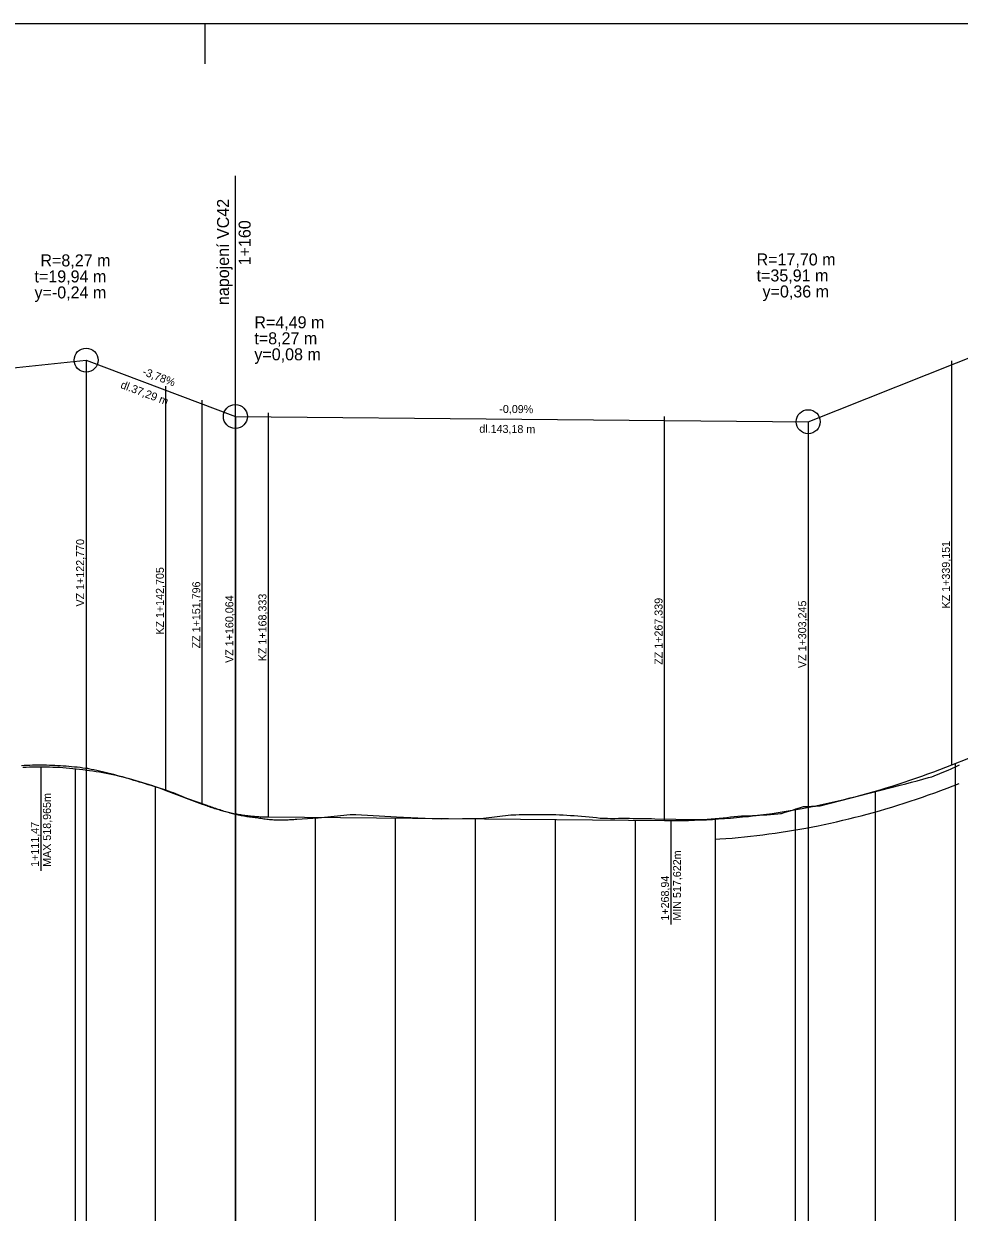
# Model space of a CAD drawing. Extents: x -632716 to -629545, y -1094726 to -1088285.
# Drawn here: x -631412.3 to -631178.5, y -1092500.3 to -1092203.3 of the extents above; entities that cross this region are included whole.
import ezdxf

# ---------------------------------------------------------------- set-up
doc = ezdxf.new("R2010")
doc.units = 0
for name, color, linetype in [('20', 7, 'Continuous'), ('Default', 7, 'Continuous'), ('formát', 7, 'Continuous'), ('PŘÍKOP', 7, 'Continuous'), ('SKLONY_NIVELETA', 7, 'Continuous'), ('SKLONY_POPIS', 7, 'Continuous'), ('TECNY_NIVELETA', 7, 'Continuous'), ('VOZOVKA', 7, 'Continuous')]:
    doc.layers.add(name, color=color, linetype=linetype)

msp = doc.modelspace()

# ---------------------------------------------------------------- linework, layer by layer
at = {"layer": '20'}
for points in [[(-631399.44, -1092389.4), (-631399.44, -1092678.62), (-631399.44, -1092728.62), (-631399.44, -1092668.62)], [(-631179.44, -1092388.14), (-631179.44, -1092678.62), (-631179.44, -1092728.62), (-631179.44, -1092668.62)], [(-631379.44, -1092393.88), (-631379.44, -1092678.62), (-631379.44, -1092728.62), (-631379.44, -1092668.62)], [(-631199.44, -1092395.04), (-631199.44, -1092678.62), (-631199.44, -1092728.62), (-631199.44, -1092668.62)], [(-631359.44, -1092400.64), (-631359.44, -1092678.62), (-631359.44, -1092728.62), (-631359.44, -1092668.62)], [(-631339.44, -1092401.6), (-631339.44, -1092678.62), (-631339.44, -1092728.62), (-631339.44, -1092668.62)], [(-631219.44, -1092399.67), (-631219.44, -1092678.62), (-631219.44, -1092728.62), (-631219.44, -1092668.62)], [(-631319.44, -1092401.78), (-631319.44, -1092678.62), (-631319.44, -1092728.62), (-631319.44, -1092668.62)], [(-631299.44, -1092401.96), (-631299.44, -1092678.62), (-631299.44, -1092728.62), (-631299.44, -1092668.62)], [(-631279.44, -1092402.14), (-631279.44, -1092678.62), (-631279.44, -1092728.62), (-631279.44, -1092668.62)], [(-631259.44, -1092402.32), (-631259.44, -1092678.62), (-631259.44, -1092728.62), (-631259.44, -1092668.62)], [(-631239.44, -1092402.05), (-631239.44, -1092678.62), (-631239.44, -1092728.62), (-631239.44, -1092668.62)]]:
    msp.add_lwpolyline(points, dxfattribs=at)
at = {"layer": 'Default'}
for p, q in [((-631180.29, -1092388.48), (-631087.13, -1092351.53)), ((-631180.29, -1092388.48), (-631087.13, -1092351.53)), ((-631376.74, -1092394.86), (-631367.65, -1092398.3)), ((-631376.74, -1092394.86), (-631367.65, -1092398.3)), ((-631351.11, -1092401.49), (-631252.11, -1092402.39)), ((-631351.11, -1092401.49), (-631252.11, -1092402.39))]:
    msp.add_line(p, q, dxfattribs=at)
for points in [[(-631412.46, -1092389.09), (-631411.63, -1092389.04), (-631410.8, -1092389.01), (-631409.97, -1092388.99), (-631409.13, -1092388.97), (-631408.3, -1092388.96), (-631407.47, -1092388.97), (-631406.64, -1092388.97), (-631405.81, -1092388.99), (-631404.98, -1092389.02), (-631404.15, -1092389.05), (-631403.32, -1092389.09), (-631402.49, -1092389.15), (-631401.66, -1092389.2), (-631400.83, -1092389.27), (-631400, -1092389.35), (-631399.17, -1092389.43), (-631398.34, -1092389.52), (-631397.51, -1092389.63), (-631395.84, -1092389.85), (-631395.01, -1092389.98), (-631394.18, -1092390.11), (-631393.35, -1092390.26), (-631392.52, -1092390.41), (-631391.69, -1092390.57), (-631390.86, -1092390.73), (-631390.03, -1092390.91), (-631389.2, -1092391.09), (-631388.37, -1092391.29), (-631387.54, -1092391.49), (-631386.71, -1092391.7), (-631385.88, -1092391.92), (-631385.05, -1092392.14), (-631384.22, -1092392.38), (-631383.38, -1092392.62), (-631382.55, -1092392.87), (-631381.72, -1092393.13), (-631380.89, -1092393.4), (-631380.06, -1092393.67), (-631379.23, -1092393.96), (-631378.4, -1092394.25), (-631377.57, -1092394.55), (-631376.74, -1092394.86)], [(-631412.46, -1092389.09), (-631411.63, -1092389.04), (-631410.8, -1092389.01), (-631409.97, -1092388.99), (-631409.13, -1092388.97), (-631408.3, -1092388.96), (-631407.47, -1092388.97), (-631406.64, -1092388.97), (-631405.81, -1092388.99), (-631404.98, -1092389.02), (-631404.15, -1092389.05), (-631403.32, -1092389.09), (-631402.49, -1092389.15), (-631401.66, -1092389.2), (-631400.83, -1092389.27), (-631400, -1092389.35), (-631399.17, -1092389.43), (-631398.34, -1092389.52), (-631397.51, -1092389.63), (-631395.84, -1092389.85), (-631395.01, -1092389.98), (-631394.18, -1092390.11), (-631393.35, -1092390.26), (-631392.52, -1092390.41), (-631391.69, -1092390.57), (-631390.86, -1092390.73), (-631390.03, -1092390.91), (-631389.2, -1092391.09), (-631388.37, -1092391.29), (-631387.54, -1092391.49), (-631386.71, -1092391.7), (-631385.88, -1092391.92), (-631385.05, -1092392.14), (-631384.22, -1092392.38), (-631383.38, -1092392.62), (-631382.55, -1092392.87), (-631381.72, -1092393.13), (-631380.89, -1092393.4), (-631380.06, -1092393.67), (-631379.23, -1092393.96), (-631378.4, -1092394.25), (-631377.57, -1092394.55), (-631376.74, -1092394.86)], [(-631252.11, -1092402.39), (-631250.61, -1092402.4), (-631249.11, -1092402.39), (-631247.62, -1092402.37), (-631246.12, -1092402.34), (-631244.63, -1092402.3), (-631243.13, -1092402.24), (-631241.63, -1092402.18), (-631240.14, -1092402.1), (-631238.64, -1092402), (-631237.15, -1092401.89), (-631235.65, -1092401.78), (-631234.15, -1092401.64), (-631232.66, -1092401.5), (-631231.16, -1092401.34), (-631229.66, -1092401.17), (-631228.17, -1092400.99), (-631226.67, -1092400.79), (-631225.18, -1092400.59), (-631223.68, -1092400.37), (-631222.18, -1092400.13), (-631220.69, -1092399.89), (-631219.19, -1092399.63), (-631217.7, -1092399.36), (-631214.7, -1092398.78), (-631213.21, -1092398.47), (-631211.71, -1092398.15), (-631210.22, -1092397.82), (-631208.72, -1092397.47), (-631207.22, -1092397.11), (-631205.73, -1092396.74), (-631204.23, -1092396.35), (-631202.74, -1092395.95), (-631201.24, -1092395.54), (-631199.74, -1092395.12), (-631198.25, -1092394.69), (-631196.75, -1092394.24), (-631195.25, -1092393.78), (-631193.76, -1092393.31), (-631192.26, -1092392.82), (-631190.77, -1092392.32), (-631189.27, -1092391.81), (-631187.77, -1092391.29), (-631186.28, -1092390.75), (-631184.78, -1092390.2), (-631183.29, -1092389.64), (-631181.79, -1092389.06), (-631180.29, -1092388.48)], [(-631252.11, -1092402.39), (-631250.61, -1092402.4), (-631249.11, -1092402.39), (-631247.62, -1092402.37), (-631246.12, -1092402.34), (-631244.63, -1092402.3), (-631243.13, -1092402.24), (-631241.63, -1092402.18), (-631240.14, -1092402.1), (-631238.64, -1092402), (-631237.15, -1092401.89), (-631235.65, -1092401.78), (-631234.15, -1092401.64), (-631232.66, -1092401.5), (-631231.16, -1092401.34), (-631229.66, -1092401.17), (-631228.17, -1092400.99), (-631226.67, -1092400.79), (-631225.18, -1092400.59), (-631223.68, -1092400.37), (-631222.18, -1092400.13), (-631220.69, -1092399.89), (-631219.19, -1092399.63), (-631217.7, -1092399.36), (-631214.7, -1092398.78), (-631213.21, -1092398.47), (-631211.71, -1092398.15), (-631210.22, -1092397.82), (-631208.72, -1092397.47), (-631207.22, -1092397.11), (-631205.73, -1092396.74), (-631204.23, -1092396.35), (-631202.74, -1092395.95), (-631201.24, -1092395.54), (-631199.74, -1092395.12), (-631198.25, -1092394.69), (-631196.75, -1092394.24), (-631195.25, -1092393.78), (-631193.76, -1092393.31), (-631192.26, -1092392.82), (-631190.77, -1092392.32), (-631189.27, -1092391.81), (-631187.77, -1092391.29), (-631186.28, -1092390.75), (-631184.78, -1092390.2), (-631183.29, -1092389.64), (-631181.79, -1092389.06), (-631180.29, -1092388.48)], [(-631367.65, -1092398.3), (-631367.3, -1092398.42), (-631366.96, -1092398.55), (-631366.62, -1092398.67), (-631366.27, -1092398.8), (-631365.93, -1092398.91), (-631365.58, -1092399.03), (-631365.24, -1092399.14), (-631364.89, -1092399.25), (-631364.55, -1092399.36), (-631364.2, -1092399.46), (-631363.86, -1092399.57), (-631363.51, -1092399.67), (-631363.17, -1092399.76), (-631362.83, -1092399.86), (-631362.48, -1092399.95), (-631362.14, -1092400.04), (-631361.79, -1092400.13), (-631361.45, -1092400.21), (-631361.1, -1092400.29), (-631360.76, -1092400.37), (-631360.41, -1092400.45), (-631360.07, -1092400.52), (-631359.72, -1092400.59), (-631359.04, -1092400.72), (-631358.69, -1092400.78), (-631358.35, -1092400.84), (-631358, -1092400.9), (-631357.66, -1092400.96), (-631357.31, -1092401.01), (-631356.97, -1092401.06), (-631356.62, -1092401.11), (-631356.28, -1092401.15), (-631355.94, -1092401.19), (-631355.59, -1092401.23), (-631355.25, -1092401.27), (-631354.9, -1092401.3), (-631354.56, -1092401.33), (-631354.21, -1092401.36), (-631353.87, -1092401.38), (-631353.52, -1092401.41), (-631353.18, -1092401.43), (-631352.83, -1092401.45), (-631352.49, -1092401.46), (-631352.15, -1092401.47), (-631351.8, -1092401.48), (-631351.46, -1092401.49), (-631351.11, -1092401.49)], [(-631367.65, -1092398.3), (-631367.3, -1092398.42), (-631366.96, -1092398.55), (-631366.62, -1092398.67), (-631366.27, -1092398.8), (-631365.93, -1092398.91), (-631365.58, -1092399.03), (-631365.24, -1092399.14), (-631364.89, -1092399.25), (-631364.55, -1092399.36), (-631364.2, -1092399.46), (-631363.86, -1092399.57), (-631363.51, -1092399.67), (-631363.17, -1092399.76), (-631362.83, -1092399.86), (-631362.48, -1092399.95), (-631362.14, -1092400.04), (-631361.79, -1092400.13), (-631361.45, -1092400.21), (-631361.1, -1092400.29), (-631360.76, -1092400.37), (-631360.41, -1092400.45), (-631360.07, -1092400.52), (-631359.72, -1092400.59), (-631359.04, -1092400.72), (-631358.69, -1092400.78), (-631358.35, -1092400.84), (-631358, -1092400.9), (-631357.66, -1092400.96), (-631357.31, -1092401.01), (-631356.97, -1092401.06), (-631356.62, -1092401.11), (-631356.28, -1092401.15), (-631355.94, -1092401.19), (-631355.59, -1092401.23), (-631355.25, -1092401.27), (-631354.9, -1092401.3), (-631354.56, -1092401.33), (-631354.21, -1092401.36), (-631353.87, -1092401.38), (-631353.52, -1092401.41), (-631353.18, -1092401.43), (-631352.83, -1092401.45), (-631352.49, -1092401.46), (-631352.15, -1092401.47), (-631351.8, -1092401.48), (-631351.46, -1092401.49), (-631351.11, -1092401.49)]]:
    msp.add_lwpolyline(points, dxfattribs=at)
at = {"layer": 'formát'}
msp.add_line((-631366.91, -1092213.28), (-631366.91, -1092203.28), dxfattribs=at)
msp.add_lwpolyline([(-632626.91, -1092797.28), (-630526.91, -1092797.28), (-630526.91, -1092203.28), (-632626.91, -1092203.28)], close=True, dxfattribs=at)
at = {"layer": 'PŘÍKOP'}
msp.add_lwpolyline([(-631239.44, -1092407.06), (-631238.31, -1092406.99), (-631236.77, -1092406.88), (-631235.23, -1092406.76), (-631233.69, -1092406.62), (-631232.16, -1092406.47), (-631230.62, -1092406.31), (-631229.08, -1092406.14), (-631227.54, -1092405.95), (-631226.01, -1092405.75), (-631224.47, -1092405.54), (-631222.93, -1092405.31), (-631221.39, -1092405.07), (-631219.86, -1092404.82), (-631218.32, -1092404.55), (-631216.78, -1092404.27), (-631213.72, -1092403.68), (-631212.18, -1092403.36), (-631210.64, -1092403.03), (-631209.11, -1092402.69), (-631207.57, -1092402.33), (-631206.04, -1092401.97), (-631204.5, -1092401.58), (-631202.97, -1092401.19), (-631201.43, -1092400.78), (-631199.9, -1092400.36), (-631198.37, -1092399.93), (-631196.83, -1092399.48), (-631195.3, -1092399.02), (-631193.77, -1092398.55), (-631192.23, -1092398.07), (-631190.7, -1092397.57), (-631189.17, -1092397.06), (-631187.64, -1092396.54), (-631186.1, -1092396), (-631184.57, -1092395.45), (-631183.04, -1092394.89), (-631181.51, -1092394.31), (-631179.98, -1092393.73), (-631178.47, -1092393.13)], dxfattribs=at)
at = {"layer": 'SKLONY_NIVELETA'}
for p, q in [((-631216.2, -1092302.72), (-631030.23, -1092228.97)), ((-631359.44, -1092241.25), (-631359.44, -1092400.64)), ((-631500.1, -1092298.14), (-631396.67, -1092287.33)), ((-631396.67, -1092287.33), (-631396.67, -1092728.62)), ((-631396.67, -1092287.33), (-631359.38, -1092301.42)), ((-631359.38, -1092301.42), (-631359.38, -1092728.62)), ((-631359.38, -1092301.42), (-631216.2, -1092302.72)), ((-631216.2, -1092302.72), (-631216.2, -1092728.62)), ((-631180.29, -1092388.48), (-631087.13, -1092351.53)), ((-631376.74, -1092394.86), (-631367.65, -1092398.3)), ((-631351.11, -1092401.49), (-631252.11, -1092402.39))]:
    msp.add_line(p, q, dxfattribs=at)
for points in [[(-631412.46, -1092389.09), (-631411.63, -1092389.04), (-631410.8, -1092389.01), (-631409.97, -1092388.99), (-631409.13, -1092388.97), (-631408.3, -1092388.96), (-631407.47, -1092388.97), (-631406.64, -1092388.97), (-631405.81, -1092388.99), (-631404.98, -1092389.02), (-631404.15, -1092389.05), (-631403.32, -1092389.09), (-631402.49, -1092389.15), (-631401.66, -1092389.2), (-631400.83, -1092389.27), (-631400, -1092389.35), (-631399.17, -1092389.43), (-631398.34, -1092389.52), (-631397.51, -1092389.63), (-631395.84, -1092389.85), (-631395.01, -1092389.98), (-631394.18, -1092390.11), (-631393.35, -1092390.26), (-631392.52, -1092390.41), (-631391.69, -1092390.57), (-631390.86, -1092390.73), (-631390.03, -1092390.91), (-631389.2, -1092391.09), (-631388.37, -1092391.29), (-631387.54, -1092391.49), (-631386.71, -1092391.7), (-631385.88, -1092391.92), (-631385.05, -1092392.14), (-631384.22, -1092392.38), (-631383.38, -1092392.62), (-631382.55, -1092392.87), (-631381.72, -1092393.13), (-631380.89, -1092393.4), (-631380.06, -1092393.67), (-631379.23, -1092393.96), (-631378.4, -1092394.25), (-631377.57, -1092394.55), (-631376.74, -1092394.86)], [(-631252.11, -1092402.39), (-631250.61, -1092402.4), (-631249.11, -1092402.39), (-631247.62, -1092402.37), (-631246.12, -1092402.34), (-631244.63, -1092402.3), (-631243.13, -1092402.24), (-631241.63, -1092402.18), (-631240.14, -1092402.1), (-631238.64, -1092402), (-631237.15, -1092401.89), (-631235.65, -1092401.78), (-631234.15, -1092401.64), (-631232.66, -1092401.5), (-631231.16, -1092401.34), (-631229.66, -1092401.17), (-631228.17, -1092400.99), (-631226.67, -1092400.79), (-631225.18, -1092400.59), (-631223.68, -1092400.37), (-631222.18, -1092400.13), (-631220.69, -1092399.89), (-631219.19, -1092399.63), (-631217.7, -1092399.36), (-631214.7, -1092398.78), (-631213.21, -1092398.47), (-631211.71, -1092398.15), (-631210.22, -1092397.82), (-631208.72, -1092397.47), (-631207.22, -1092397.11), (-631205.73, -1092396.74), (-631204.23, -1092396.35), (-631202.74, -1092395.95), (-631201.24, -1092395.54), (-631199.74, -1092395.12), (-631198.25, -1092394.69), (-631196.75, -1092394.24), (-631195.25, -1092393.78), (-631193.76, -1092393.31), (-631192.26, -1092392.82), (-631190.77, -1092392.32), (-631189.27, -1092391.81), (-631187.77, -1092391.29), (-631186.28, -1092390.75), (-631184.78, -1092390.2), (-631183.29, -1092389.64), (-631181.79, -1092389.06), (-631180.29, -1092388.48)], [(-631367.65, -1092398.3), (-631367.3, -1092398.42), (-631366.96, -1092398.55), (-631366.62, -1092398.67), (-631366.27, -1092398.8), (-631365.93, -1092398.91), (-631365.58, -1092399.03), (-631365.24, -1092399.14), (-631364.89, -1092399.25), (-631364.55, -1092399.36), (-631364.2, -1092399.46), (-631363.86, -1092399.57), (-631363.51, -1092399.67), (-631363.17, -1092399.76), (-631362.83, -1092399.86), (-631362.48, -1092399.95), (-631362.14, -1092400.04), (-631361.79, -1092400.13), (-631361.45, -1092400.21), (-631361.1, -1092400.29), (-631360.76, -1092400.37), (-631360.41, -1092400.45), (-631360.07, -1092400.52), (-631359.72, -1092400.59), (-631359.04, -1092400.72), (-631358.69, -1092400.78), (-631358.35, -1092400.84), (-631358, -1092400.9), (-631357.66, -1092400.96), (-631357.31, -1092401.01), (-631356.97, -1092401.06), (-631356.62, -1092401.11), (-631356.28, -1092401.15), (-631355.94, -1092401.19), (-631355.59, -1092401.23), (-631355.25, -1092401.27), (-631354.9, -1092401.3), (-631354.56, -1092401.33), (-631354.21, -1092401.36), (-631353.87, -1092401.38), (-631353.52, -1092401.41), (-631353.18, -1092401.43), (-631352.83, -1092401.45), (-631352.49, -1092401.46), (-631352.15, -1092401.47), (-631351.8, -1092401.48), (-631351.46, -1092401.49), (-631351.11, -1092401.49)]]:
    msp.add_lwpolyline(points, dxfattribs=at)
for centre in [(-631396.67, -1092287.33), (-631359.38, -1092301.42), (-631216.2, -1092302.72)]:
    msp.add_circle(centre, 3, dxfattribs=at)
at = {"layer": 'TECNY_NIVELETA'}
for p, q in [((-631396.67, -1092287.33), (-631396.67, -1092287.33)), ((-631180.29, -1092388.48), (-631180.29, -1092287.48)), ((-631376.74, -1092394.86), (-631376.74, -1092293.86)), ((-631367.65, -1092398.3), (-631367.65, -1092297.3)), ((-631351.11, -1092401.49), (-631351.11, -1092300.49)), ((-631359.38, -1092301.42), (-631359.38, -1092301.42)), ((-631252.11, -1092402.39), (-631252.11, -1092301.39)), ((-631216.2, -1092302.72), (-631216.2, -1092302.72)), ((-631407.97, -1092388.96), (-631407.97, -1092414.96)), ((-631250.5, -1092402.4), (-631250.5, -1092428.4))]:
    msp.add_line(p, q, dxfattribs=at)
at = {"layer": 'VOZOVKA'}
msp.add_lwpolyline([(-631412.84, -1092388.61), (-631412.14, -1092388.57), (-631411.45, -1092388.54), (-631410.75, -1092388.52), (-631410.05, -1092388.5), (-631409.35, -1092388.49), (-631408.66, -1092388.48), (-631407.96, -1092388.48), (-631407.26, -1092388.49), (-631406.57, -1092388.5), (-631405.87, -1092388.52), (-631405.17, -1092388.54), (-631404.47, -1092388.57), (-631403.78, -1092388.61), (-631403.08, -1092388.65), (-631402.38, -1092388.69), (-631401.69, -1092388.75), (-631400.99, -1092388.8), (-631400.29, -1092388.87), (-631399.59, -1092388.94), (-631398.9, -1092389.01), (-631398.2, -1092389.09), (-631397.5, -1092389.18), (-631396.8, -1092389.27), (-631396.34, -1092389.34), (-631396.11, -1092389.38), (-631395.41, -1092389.52), (-631394.71, -1092389.67), (-631394.02, -1092389.81), (-631393.32, -1092389.97), (-631392.62, -1092390.13), (-631391.92, -1092390.3), (-631391.23, -1092390.47), (-631390.53, -1092390.64), (-631389.82, -1092390.83), (-631389.1, -1092391.02), (-631388.39, -1092391.22), (-631387.67, -1092391.42), (-631386.96, -1092391.63), (-631386.24, -1092391.84), (-631385.53, -1092392.05), (-631384.82, -1092392.26), (-631384.1, -1092392.48), (-631383.39, -1092392.7), (-631382.67, -1092392.92), (-631381.96, -1092393.14), (-631381.24, -1092393.37), (-631380.53, -1092393.59), (-631376.85, -1092394.74), (-631375.5, -1092395.24), (-631374.93, -1092395.36), (-631371.62, -1092396.76), (-631366.5, -1092398.56), (-631366.15, -1092398.69), (-631365.79, -1092398.81), (-631365.43, -1092398.94), (-631365.08, -1092399.06), (-631364.72, -1092399.19), (-631364.36, -1092399.31), (-631364, -1092399.43), (-631363.65, -1092399.55), (-631363.29, -1092399.67), (-631362.93, -1092399.78), (-631362.58, -1092399.9), (-631362.22, -1092400.01), (-631361.86, -1092400.12), (-631361.5, -1092400.22), (-631361.15, -1092400.33), (-631360.79, -1092400.43), (-631360.44, -1092400.52), (-631360.08, -1092400.61), (-631359.72, -1092400.7), (-631359.37, -1092400.79), (-631359.01, -1092400.87), (-631358.66, -1092400.95), (-631358.3, -1092401.02), (-631357.95, -1092401.09), (-631357.59, -1092401.16), (-631357.23, -1092401.22), (-631356.88, -1092401.28), (-631356.52, -1092401.34), (-631356.17, -1092401.39), (-631355.81, -1092401.44), (-631355.46, -1092401.48), (-631355.1, -1092401.52), (-631354.8, -1092401.55), (-631354.74, -1092401.56), (-631354.39, -1092401.6), (-631354.07, -1092401.63), (-631354.03, -1092401.64), (-631353.68, -1092401.71), (-631353.32, -1092401.77), (-631352.97, -1092401.83), (-631352.61, -1092401.89), (-631352.25, -1092401.94), (-631351.9, -1092401.99), (-631351.54, -1092402.03), (-631351.19, -1092402.07), (-631350.83, -1092402.1), (-631350.48, -1092402.13), (-631350.12, -1092402.16), (-631349.76, -1092402.18), (-631349.41, -1092402.2), (-631349.05, -1092402.21), (-631348.7, -1092402.22), (-631348.34, -1092402.22), (-631347.98, -1092402.22), (-631347.62, -1092402.22), (-631347.27, -1092402.21), (-631346.91, -1092402.2), (-631346.55, -1092402.19), (-631346.2, -1092402.18), (-631345.84, -1092402.16), (-631345.48, -1092402.14), (-631345.12, -1092402.12), (-631344.77, -1092402.1), (-631344.41, -1092402.08), (-631344.05, -1092402.06), (-631338.69, -1092401.74), (-631330.65, -1092400.92), (-631329.27, -1092400.86), (-631319.13, -1092401.49), (-631310.23, -1092401.89), (-631307.97, -1092401.98), (-631297.35, -1092401.81), (-631290.51, -1092400.96), (-631290.23, -1092400.95), (-631289.32, -1092400.93), (-631288.41, -1092400.92), (-631287.51, -1092400.9), (-631286.6, -1092400.89), (-631285.69, -1092400.88), (-631284.78, -1092400.87), (-631283.87, -1092400.86), (-631282.96, -1092400.86), (-631282.05, -1092400.87), (-631281.14, -1092400.88), (-631280.23, -1092400.89), (-631279.31, -1092400.92), (-631278.38, -1092400.95), (-631277.46, -1092400.99), (-631276.53, -1092401.03), (-631275.61, -1092401.09), (-631274.68, -1092401.14), (-631273.75, -1092401.21), (-631272.83, -1092401.28), (-631271.9, -1092401.36), (-631270.98, -1092401.45), (-631270.05, -1092401.55), (-631269.13, -1092401.65), (-631268.2, -1092401.76), (-631268.01, -1092401.78), (-631267.28, -1092401.8), (-631266.35, -1092401.83), (-631265.66, -1092401.86), (-631265.43, -1092401.85), (-631264.5, -1092401.84), (-631263.59, -1092401.83), (-631262.68, -1092401.82), (-631261.77, -1092401.83), (-631260.86, -1092401.83), (-631259.95, -1092401.84), (-631259.05, -1092401.85), (-631258.14, -1092401.87), (-631257.23, -1092401.88), (-631256.32, -1092401.9), (-631255.41, -1092401.92), (-631254.5, -1092401.94), (-631244.08, -1092402.17), (-631242.72, -1092402.13), (-631242.43, -1092402.11), (-631241.43, -1092402.03), (-631241.28, -1092402.02), (-631240.43, -1092401.95), (-631239.43, -1092401.87), (-631238.43, -1092401.78), (-631237.43, -1092401.68), (-631236.52, -1092401.59), (-631235.61, -1092401.5), (-631234.71, -1092401.4), (-631233.8, -1092401.29), (-631233.67, -1092401.28), (-631232.89, -1092401.25), (-631231.98, -1092401.22), (-631231.07, -1092401.19), (-631230.16, -1092401.14), (-631229.25, -1092401.1), (-631228.35, -1092401.05), (-631227.44, -1092400.99), (-631226.53, -1092400.93), (-631225.62, -1092400.86), (-631224.71, -1092400.79), (-631223.8, -1092400.72), (-631223.14, -1092400.66), (-631222.9, -1092400.59), (-631221.99, -1092400.32), (-631221.08, -1092400.05), (-631220.17, -1092399.78), (-631219.26, -1092399.5), (-631218.35, -1092399.22), (-631217.35, -1092398.9), (-631217.32, -1092398.89), (-631216.35, -1092398.86), (-631215.35, -1092398.82), (-631214.35, -1092398.79), (-631213.35, -1092398.75), (-631213.23, -1092398.74), (-631193.24, -1092393.55), (-631191.83, -1092393.18), (-631190.41, -1092392.8), (-631189, -1092392.43), (-631187.58, -1092392.05), (-631186.17, -1092391.67), (-631185.28, -1092391.43), (-631184.75, -1092391.22), (-631183.34, -1092390.64), (-631181.92, -1092390.06), (-631181.21, -1092389.77), (-631180.51, -1092389.44), (-631179.09, -1092388.77), (-631178.37, -1092388.43)], dxfattribs=at)

# ---------------------------------------------------------------- texts
at = {"layer": 'SKLONY_POPIS'}
for s, height, rotation, p in [('napojení VC42', 3, 90, (-631360.96, -1092273.57)), ('1+160', 3, 90, (-631355.56, -1092263.65)), ('-3,78%', 2, 339.3071, (-631382.76, -1092290.98)), ('dl.37,29 m', 2, 339.3071, (-631388.24, -1092294.26)), ('-0,09%', 2, 359.4808, (-631293.41, -1092300.52)), ('dl.143,18 m', 2, 359.4808, (-631298.41, -1092305.47)), ('VZ 1+122,770', 2, 90, (-631397.17, -1092348.91)), ('KZ 1+339,151', 2, 90, (-631180.79, -1092349.39)), ('KZ 1+142,705', 2, 90, (-631377.24, -1092355.94)), ('ZZ 1+151,796', 2, 90, (-631368.15, -1092359.38)), ('VZ 1+160,064', 2, 90, (-631359.88, -1092363)), ('KZ 1+168,333', 2, 90, (-631351.61, -1092362.58)), ('ZZ 1+267,339', 2, 90, (-631252.61, -1092363.47)), ('VZ 1+303,245', 2, 90, (-631216.7, -1092364.3)), ('MAX 518,965m', 2, 90, (-631405.47, -1092413.96)), ('1+111,47', 2, 90, (-631408.47, -1092413.96)), ('MIN 517,622m', 2, 90, (-631248, -1092427.4)), ('1+268,94', 2, 90, (-631251, -1092427.4))]:
    msp.add_text(s, height=height, rotation=rotation, dxfattribs=at).set_placement(p)
for s, p in [('R=8,27 m', (-631408.1, -1092263.91)), ('R=17,70 m', (-631229.11, -1092263.67)), ('t=19,94 m', (-631409.58, -1092267.91)), ('t=35,91 m', (-631229.11, -1092267.67)), ('y=-0,24 m', (-631409.58, -1092271.91)), ('y=0,36 m', (-631227.62, -1092271.67)), ('R=4,49 m', (-631354.63, -1092279.38)), ('t=8,27 m', (-631354.63, -1092283.38)), ('y=0,08 m', (-631354.63, -1092287.38))]:
    msp.add_text(s, height=3, dxfattribs=at).set_placement(p)

doc.saveas('drawing.dxf')
